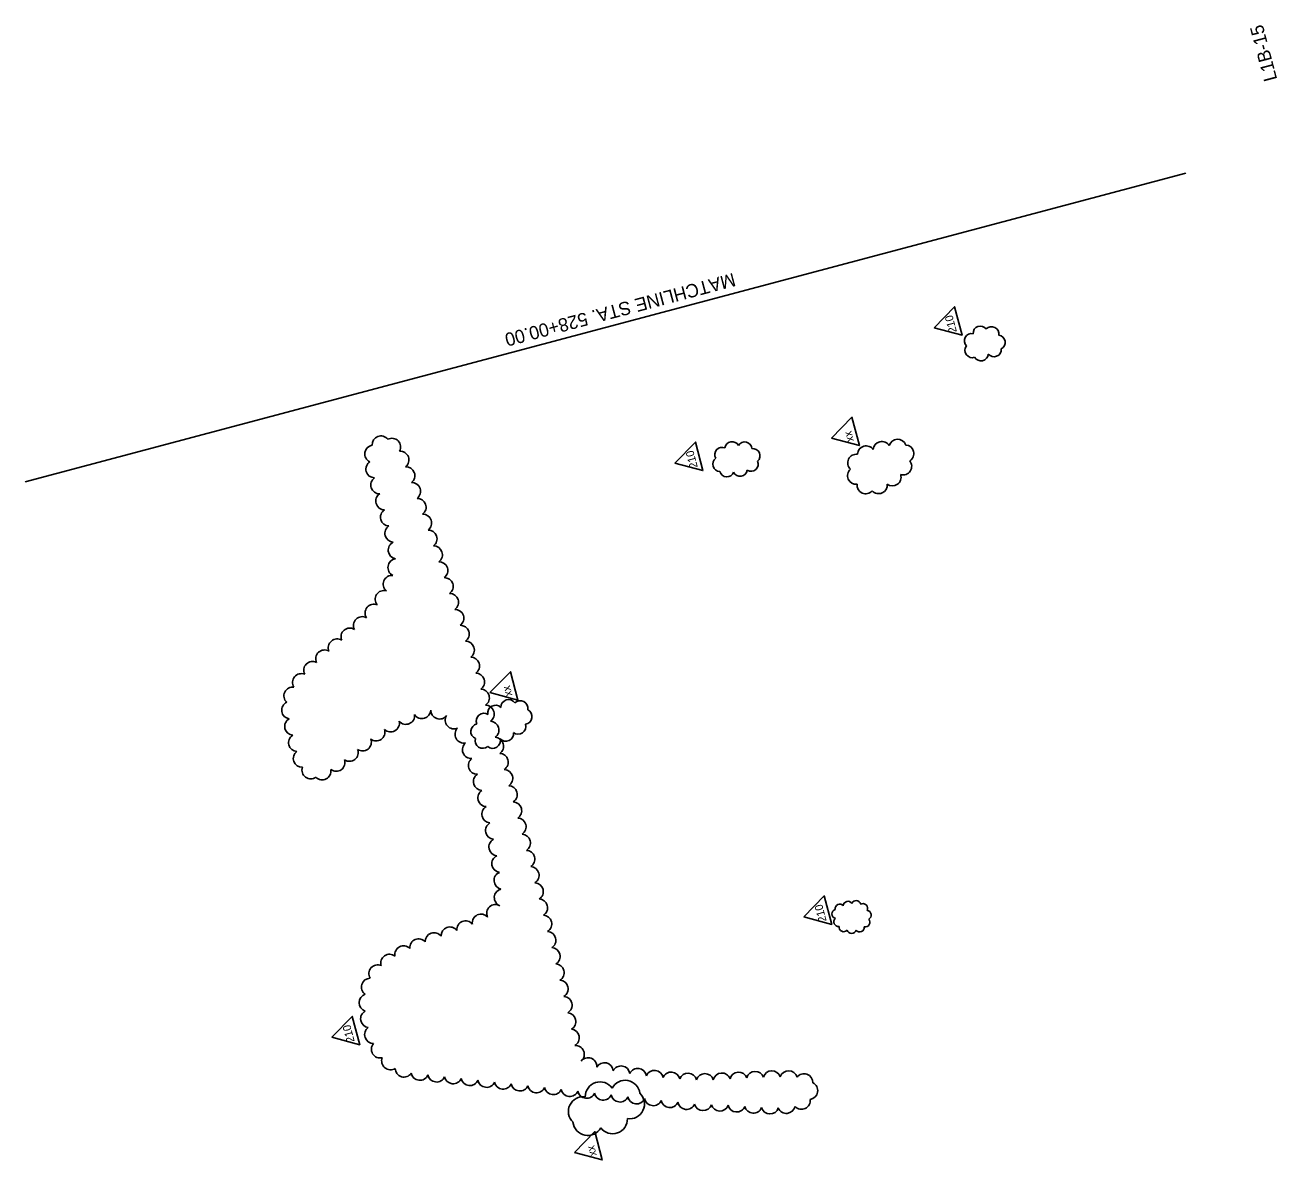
# Model space of a CAD drawing. Extents: x 930394 to 931429, y 627795 to 629076.
# Drawn here: x 930394 to 931144, y 628396 to 629076 of the extents above; entities that cross this region are included whole.
import ezdxf

# ---------------------------------------------------------------- set-up
doc = ezdxf.new("R2010")
doc.units = 0
for name, color, linetype in [('Cloud_dp', 7, 'Continuous'), ('MatchLines_dp', 7, 'Continuous'), ('TextShtNo', 7, 'Continuous')]:
    doc.layers.add(name, color=color, linetype=linetype)

msp = doc.modelspace()

# ---------------------------------------------------------------- linework, layer by layer
at = {"layer": 'Cloud_dp'}
for points in [[(930938.83, 628895.01), (930955.58, 628890.52), (930951.06, 628907.59)], [(930877.34, 628828.77), (930894.09, 628824.29), (930889.57, 628841.35)], [(930783.51, 628813.85), (930800.26, 628809.37), (930795.74, 628826.43)], [(930672.61, 628676.17), (930689.36, 628671.69), (930684.85, 628688.75)], [(930860.73, 628541.71), (930877.48, 628537.23), (930872.96, 628554.29)], [(930577.83, 628469.5), (930594.58, 628465.02), (930590.07, 628482.08)], [(930723.2, 628400.44), (930739.95, 628395.96), (930735.43, 628413.02)]]:
    msp.add_lwpolyline(points, close=True, dxfattribs=at)
for centre, radius, start, end in [((930961.36, 628887.1), 4.4, 79.11621, 224.11621), ((930966.59, 628891.58), 4.4, 37.04917, 182.04917), ((930973.3, 628891.21), 4.4, 351.53714, 136.53714), ((930977.07, 628886.19), 4.4, 297.45043, 82.45043), ((930961.74, 628881.42), 4.4, 143.5281, 288.5281), ((930974.72, 628881.96), 4.4, 219.22064, 4.22064), ((930966.92, 628879.5), 4.4, 210.74985, 355.74985), ((930607.25, 628824.87), 5.27, 38.06382, 183.06382), ((930613.79, 628823.42), 5.27, 331.94744, 116.94744), ((930602.87, 628819.4), 5.27, 99.66133, 244.66133), ((930618.78, 628815.69), 5.27, 308.78451, 93.78451), ((930811.7, 628818.95), 4.33, 65.71325, 210.71325), ((930817.77, 628822.35), 4.33, 27.8479, 172.8479), ((930825.32, 628822.17), 4.33, 4.44172, 149.44172), ((930830.15, 628818.21), 4.33, 311.83887, 96.83887), ((930898.12, 628818.99), 5.17, 33.90672, 178.90672), ((930907.57, 628821.59), 5.17, 31.82335, 176.82335), ((930916.93, 628822.92), 5.17, 19.39709, 164.39709), ((930921.53, 628819.48), 5.17, 301.91699, 86.91699), ((930603.52, 628810.24), 5.27, 123.40488, 268.40488), ((930810.45, 628813.18), 4.33, 124.80664, 269.80664), ((930829.08, 628813.25), 4.33, 238.72194, 23.72194), ((930892.26, 628813.97), 5.17, 82.1992, 227.1992), ((930920.24, 628811.85), 5.17, 253.88267, 38.88267), ((930622.32, 628806.32), 5.27, 307.57822, 92.57822), ((930814.64, 628809.88), 4.33, 193.66618, 338.66618), ((930822.55, 628810.21), 4.33, 206.17177, 351.17177), ((930892.13, 628806.27), 5.17, 130.9028, 275.9028), ((930913.88, 628805.32), 5.17, 232.60729, 17.60729), ((930606.45, 628800.69), 5.27, 125.69137, 270.69137), ((930625.72, 628796.88), 5.27, 307.06611, 92.06611), ((930897.8, 628800.62), 5.16, 174.31574, 319.31574), ((930905.6, 628800.66), 5.17, 221.16971, 6.16971), ((930609.45, 628791.05), 5.27, 123.96668, 268.96668), ((930629.06, 628787.41), 5.27, 306.75332, 91.75332), ((930612.24, 628781.37), 5.27, 123.09941, 268.09941), ((930614.9, 628771.67), 5.27, 122.55441, 267.55441), ((930632.35, 628777.92), 5.27, 306.53756, 91.53756), ((930635.62, 628768.42), 5.27, 306.38338, 91.38338), ((930616.88, 628761.62), 5.27, 114.83978, 259.83978), ((930638.86, 628758.91), 5.27, 306.26609, 91.26609), ((930616.74, 628751.23), 5.27, 98.56046, 243.56046), ((930642.08, 628749.4), 5.27, 306.17297, 91.17297), ((930613.92, 628741.26), 5.27, 84.78999, 229.78999), ((930645.29, 628739.88), 5.27, 306.09672, 91.09672), ((930609.11, 628732.16), 5.27, 74.58434, 219.58434), ((930648.49, 628730.35), 5.27, 306.03278, 91.03278), ((930603.02, 628723.94), 5.27, 67.26454, 212.26454), ((930651.68, 628720.82), 5.27, 305.97816, 90.97816), ((930596.08, 628716.48), 5.27, 61.9215, 206.9215), ((930654.86, 628711.29), 5.27, 305.90643, 90.90643), ((930588.59, 628709.63), 5.27, 58.01857, 203.01857), ((930573.45, 628696.49), 5.27, 59.76902, 204.76902), ((930580.95, 628703.1), 5.27, 57.96203, 202.96203), ((930658, 628701.76), 5.27, 305.51076, 90.51076), ((930566.23, 628689.61), 5.27, 62.54548, 207.54548), ((930661.06, 628692.2), 5.27, 305.06956, 90.06956), ((930559.56, 628682.3), 5.27, 67.6205, 212.6205), ((930664.06, 628682.62), 5.27, 304.68855, 89.68855), ((930554.38, 628674.25), 5.27, 81.9071, 226.9071), ((930667, 628673.02), 5.27, 304.35523, 89.35523), ((930683.77, 628667.4), 4.61, 35.57457, 180.57457), ((930690.73, 628666.78), 4.61, 349.23692, 134.23692), ((930553.06, 628665.65), 5.27, 115.66746, 260.66746), ((930631.85, 628665.87), 5.27, 213.35065, 358.35065), ((930642.38, 628665.59), 5.27, 178.53623, 323.53623), ((930669.02, 628659.22), 4.61, 58.30599, 203.30599), ((930669.89, 628663.4), 5.27, 304.06043, 89.06043), ((930675.96, 628664.03), 4.61, 46.10262, 191.10262), ((930693.21, 628661.79), 4.61, 278.6372, 63.6372), ((930554.84, 628655.89), 5.27, 120.00317, 265.00317), ((930613.07, 628657.9), 5.27, 226.80427, 11.80427), ((930622.21, 628662.43), 5.27, 220.9603, 5.9603), ((930651.1, 628659.69), 5.27, 148.35803, 293.35803), ((930665.72, 628652.88), 4.61, 101.67952, 246.67952), ((930672.73, 628653.77), 5.27, 303.79728, 88.79728), ((930689.51, 628655.84), 4.61, 232.5707, 17.5707), ((930557.15, 628646.16), 5.27, 121.68226, 266.68226), ((930596.24, 628646.51), 5.27, 235.95461, 20.95461), ((930604.42, 628652.53), 5.27, 231.82646, 16.82646), ((930656.99, 628651.2), 5.27, 136.08337, 281.08337), ((930668.33, 628647.42), 4.61, 164.49119, 309.49119), ((930674.24, 628647.38), 4.61, 229.80899, 14.80899), ((930675.53, 628644.12), 5.27, 303.56051, 88.56051), ((930682.13, 628651.63), 4.61, 221.79772, 6.79772), ((930560.01, 628636.69), 5.27, 127.00493, 272.00493), ((930588.37, 628640.26), 5.27, 235.87181, 20.87181), ((930661.38, 628641.99), 5.27, 129.9086, 274.9086), ((930580.41, 628634.27), 5.27, 233.0603, 18.0603), ((930664.94, 628632.49), 5.27, 126.14262, 271.14262), ((930678.29, 628634.47), 5.27, 303.34599, 88.34599), ((930565.18, 628629.73), 5.26, 161.20431, 306.20431), ((930572.04, 628629.18), 5.27, 224.58651, 9.58651), ((930667.96, 628622.83), 5.27, 123.56725, 268.56725), ((930681.01, 628624.8), 5.27, 303.15045, 88.15045), ((930683.71, 628615.12), 5.27, 302.97126, 87.97126), ((930670.59, 628613.08), 5.27, 121.71301, 266.71301), ((930672.99, 628603.29), 5.27, 120.74626, 265.74626), ((930686.37, 628605.44), 5.27, 302.80625, 87.80625), ((930675.21, 628593.47), 5.27, 119.80758, 264.80758), ((930689.01, 628595.74), 5.27, 302.65366, 87.65366), ((930691.63, 628586.05), 5.27, 302.512, 87.512), ((930677.25, 628583.59), 5.27, 118.51217, 263.51217), ((930694.22, 628576.34), 5.27, 302.38003, 87.38003), ((930679.01, 628573.64), 5.27, 116.55761, 261.55761), ((930680.3, 628563.58), 5.27, 113.09313, 258.09313), ((930696.79, 628566.63), 5.27, 302.2567, 87.2567), ((930680.48, 628553.31), 5.27, 103.88573, 248.88573), ((930699.34, 628556.91), 5.27, 302.1563, 87.1563), ((930701.87, 628547.19), 5.27, 302.07159, 87.07159), ((930887.18, 628548.25), 2.8, 32.32565, 177.32565), ((930892.14, 628548.71), 2.8, 13.30233, 158.30233), ((930667.27, 628538.08), 5.27, 42.63665, 187.63665), ((930675.93, 628543.85), 5.27, 59.74036, 204.74036), ((930880.43, 628543.53), 2.79, 108.97672, 253.97672), ((930882.3, 628546.51), 2.8, 41.92382, 186.92382), ((930896.16, 628546.88), 2.8, 332.62493, 117.62493), ((930898.31, 628542.81), 2.8, 298.17345, 83.17345), ((930657.97, 628534.03), 5.27, 39.34872, 184.34872), ((930704.39, 628537.46), 5.27, 301.97159, 86.97159), ((930881.55, 628538.77), 2.8, 132.30012, 277.30012), ((930884.67, 628535.62), 2.79, 172.26526, 317.26526), ((930897.58, 628538.44), 2.8, 257.85795, 42.85795), ((930629.83, 628523.32), 5.27, 40.45844, 185.45844), ((930639.1, 628526.97), 5.27, 37.53077, 182.53077), ((930648.55, 628530.42), 5.27, 37.61274, 182.61274), ((930706.89, 628527.73), 5.27, 301.85081, 86.85081), ((930889.4, 628534.55), 2.8, 197.09283, 342.09283), ((930894.21, 628535.48), 2.8, 219.7759, 4.7759), ((930620.85, 628519.1), 5.27, 44.86785, 189.86785), ((930709.37, 628518), 5.27, 301.70085, 86.70085), ((930612.42, 628514.04), 5.27, 52.05324, 197.05324), ((930711.82, 628508.26), 5.27, 301.50767, 86.50767), ((930605.27, 628507.67), 5.27, 66.36862, 211.36862), ((930600.82, 628499.66), 5.27, 90.51822, 235.51822), ((930714.23, 628498.51), 5.27, 301.24539, 86.24539), ((930599.45, 628490.3), 5.27, 107.74865, 252.74865), ((930716.58, 628488.75), 5.27, 300.8593, 85.8593), ((930600.34, 628480.61), 5.27, 117.78101, 262.78101), ((930718.84, 628478.97), 5.27, 300.20355, 85.20355), ((930602.76, 628471.1), 5.27, 125.73944, 270.73944), ((930720.91, 628469.18), 5.27, 298.63018, 83.63018), ((930606.79, 628462.37), 5.27, 138.86726, 283.86726), ((930723.92, 628459.32), 5.27, 310.38016, 95.38016), ((930612.95, 628455.31), 5.27, 158.32866, 303.32866), ((930731.44, 628452), 5.27, 356.21767, 141.21767), ((930741.25, 628449), 5.27, 4.79016, 149.79016), ((930621.11, 628450.93), 5.27, 180.26432, 325.26432), ((930630.6, 628449), 5.27, 191.69766, 336.69766), ((930640.6, 628447.97), 5.27, 191.55414, 336.55414), ((930650.6, 628446.92), 5.27, 191.43501, 336.43501), ((930751.21, 628447.07), 5.27, 8.23664, 153.23664), ((930761.2, 628445.59), 5.27, 9.94692, 154.94692), ((930771.2, 628444.37), 5.27, 11.14285, 156.14285), ((930781.25, 628443.39), 5.27, 12.67644, 157.67644), ((930791.33, 628442.72), 5.27, 14.74343, 159.74343), ((930801.46, 628442.5), 5.27, 17.73398, 162.73398), ((930811.58, 628442.82), 5.27, 20.8889, 165.8889), ((930821.61, 628443.38), 5.27, 20.46053, 165.46053), ((930831.63, 628443.83), 5.27, 19.74826, 164.74826), ((930841.65, 628444.16), 5.27, 19.04813, 164.04813), ((930851.61, 628444.16), 5.27, 15.9076, 160.9076), ((930860.88, 628442.42), 5.27, 357.82525, 142.82525), ((930660.6, 628445.85), 5.27, 191.36364, 336.36364), ((930670.59, 628444.77), 5.27, 191.31472, 336.31472), ((930680.58, 628443.68), 5.27, 191.27848, 336.27848), ((930690.57, 628442.59), 5.27, 191.25024, 336.25024), ((930700.56, 628441.5), 5.27, 191.22742, 336.22742), ((930710.55, 628440.4), 5.27, 191.20849, 336.20849), ((930720.54, 628439.29), 5.27, 191.19268, 336.19268), ((930738.61, 628433.89), 8.88, 35.6123, 180.6123), ((930753.66, 628434.89), 8.87, 6.944, 151.944), ((930863.8, 628437.51), 5.27, 278.52637, 63.52637), ((930728.47, 628425.01), 8.87, 81.77379, 226.77379), ((930730.53, 628438.19), 5.27, 191.18773, 336.18773), ((930740.52, 628437.08), 5.27, 191.18773, 336.18773), ((930750.51, 628435.98), 5.27, 191.18773, 336.18773), ((930756.35, 628429.53), 8.88, 261.46323, 46.46323), ((930760.49, 628434.87), 5.27, 191.18773, 336.18773), ((930770.48, 628433.77), 5.27, 191.18773, 336.18773), ((930780.47, 628432.66), 5.27, 191.18773, 336.18773), ((930859.35, 628431.61), 5.27, 222.54854, 7.54854), ((930790.46, 628431.56), 5.27, 191.18773, 336.18773), ((930800.36, 628430.84), 5.27, 195.44978, 340.44978), ((930810.4, 628430.5), 5.27, 195.66426, 340.66426), ((930820.49, 628429.99), 5.27, 193.63593, 338.63593), ((930830.52, 628429.29), 5.27, 193.3664, 338.3664), ((930840.48, 628428.82), 5.27, 196.23678, 341.23678), ((930850.32, 628429.16), 5.27, 202.7343, 347.7343), ((930731.21, 628419.54), 8.88, 186.40976, 331.40976), ((930746.16, 628420.55), 8.88, 216.30499, 1.30499)]:
    msp.add_arc(centre, radius, start, end, dxfattribs=at)
at = {"layer": 'MatchLines_dp'}
msp.add_lwpolyline([(931089.74, 628987.65), (930741.83, 628895.14), (930393.92, 628802.63)], dxfattribs=at)

# ---------------------------------------------------------------- texts
at = {"layer": 'Cloud_dp'}
for s, p in [('210', (930952.54, 628892.57)), ('xx', (930890.82, 628827.19)), ('210', (930797.22, 628811.42)), ('xx', (930686.1, 628674.59)), ('210', (930874.44, 628539.28)), ('210', (930591.55, 628467.07)), ('xx', (930736.68, 628398.87))]:
    msp.add_text(s, height=4.799, rotation=104.82565, dxfattribs=at).set_placement(p)
at = {"layer": 'MatchLines_dp'}
msp.add_text('MATCHLINE STA. 528+00.00', height=8, rotation=194.89045, dxfattribs=at).set_placement((930818.49, 628927.94))
at = {"layer": 'TextShtNo'}
msp.add_text('L1B-15', height=8, rotation=104.82565, dxfattribs=at).set_placement((931144.59, 629043.92))

doc.saveas('drawing.dxf')
